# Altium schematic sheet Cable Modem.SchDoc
size B
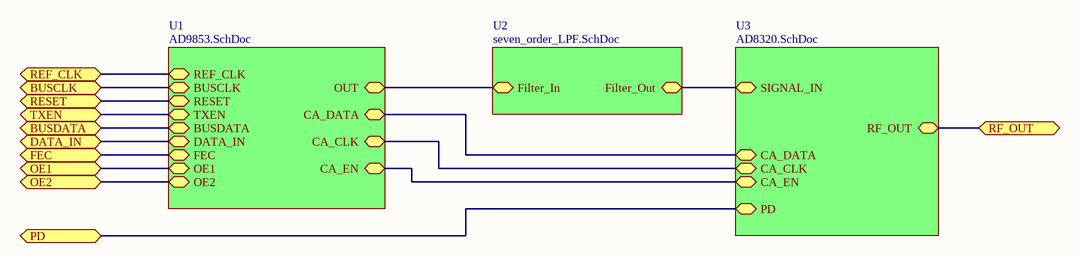
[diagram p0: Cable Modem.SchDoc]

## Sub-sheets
U1 = AD9853.SchDoc: REF_CLK, BUSCLK, RESET, TXEN, BUSDATA, OE1, OE2, DATA_IN, FEC, OUT, CA_DATA, CA_CLK, CA_EN
U2 = seven_order_LPF.SchDoc: Filter_Out, Filter_In
U3 = AD8320.SchDoc: SIGNAL_IN, CA_DATA, CA_EN, CA_CLK, PD, RF_OUT

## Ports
BUSCLK, BUSDATA, DATA_IN, FEC, OE1, OE2, PD, REF_CLK, RESET, RF_OUT, TXEN

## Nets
BUSCLK: port BUSCLK, sheet U1/BUSCLK
BUSDATA: port BUSDATA, sheet U1/BUSDATA
DATA_IN: port DATA_IN, sheet U1/DATA_IN
FEC: port FEC, sheet U1/FEC
OE1: port OE1, sheet U1/OE1
OE2: port OE2, sheet U1/OE2
PD: port PD, sheet U3/PD
REF_CLK: port REF_CLK, sheet U1/REF_CLK
RESET: port RESET, sheet U1/RESET
RF_OUT: port RF_OUT, sheet U3/RF_OUT
TXEN: port TXEN, sheet U1/TXEN
(unnamed): sheet U1/OUT, sheet U2/Filter_In
(unnamed): sheet U1/CA_DATA, sheet U3/CA_DATA  [a separate net that carries the same name]
(unnamed): sheet U1/CA_CLK, sheet U3/CA_CLK  [a separate net that carries the same name]
(unnamed): sheet U1/CA_EN, sheet U3/CA_EN  [a separate net that carries the same name]
(unnamed): sheet U2/Filter_Out, sheet U3/SIGNAL_IN  [a separate net that carries the same name]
